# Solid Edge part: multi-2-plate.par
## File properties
Author: Deepak Maini
Template: normal.par
Last saved by: MYPC
Revision: 5
Application: Solid Edge
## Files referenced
..\multi-cutout.asm
ED:\sld-edg-15\cd-models\c09-sld-edg-15\figure28-8&29\multi-cutout.asm
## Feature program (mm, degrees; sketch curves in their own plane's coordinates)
sketch for "unnamed Protrusion 1" plane through (0, 0, 0) normal (0, 0, 1) x-axis (1, 0, 0)
  line (-46.224, -15.84) -> (-46.224, 16.704)
  line (-46.224, 16.704) -> (47.664, 16.704)
  line (47.664, 16.704) -> (47.664, -15.84)
  line (47.664, -15.84) -> (-46.224, -15.84)
extrude "unnamed Protrusion 1" add finite 10.6 along +normal
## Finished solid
Body 1: solid body, 6 faces, 12 edges, 8 vertices.
  Faces by surface: plane 6
  Edges by curve: line 12
Bounding box of the edges (mm): 93.888 x 32.544 x 10.600, from (-46.224, -15.84, 0) to (47.664, 16.704, 10.6).
Planar faces by outward normal: +x 1, +y 1, +z 1, -x 1, -y 1, -z 1
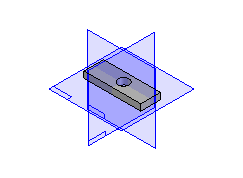
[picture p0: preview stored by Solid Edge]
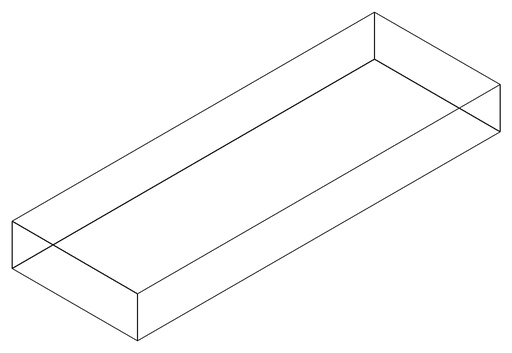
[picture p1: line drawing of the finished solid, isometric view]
